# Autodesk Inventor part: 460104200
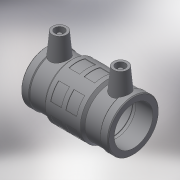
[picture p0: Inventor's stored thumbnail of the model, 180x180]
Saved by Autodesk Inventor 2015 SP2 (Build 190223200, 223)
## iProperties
Created: 2017-06
Part Number: 460104200
Material: Generic
Description: PLASSON LIGHTFIT COUPLER 200
Document SubType Name: Modeling
Designer: KIM
Mass: 89.5427 g
Surface Area: 304.58 cm^2
Volume: 89.5427 cm^3
Density: 1 g/cm^3
Appearance: Default
Author: KIM
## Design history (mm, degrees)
derived "460104.ipt"
feature "Solid1::460104.ipt"
tag "TaggingFeature1"
body "Solid1"
other parameters: "d13" = 232, "d14" = 17.6296, "d15" = 114, "d16" = 114, "d17" = 198, "d19" = 3.52592, "d20" = 168 deg, "d22" = 220.9, "d23" = 235, "d24" = 214.273, "d25" = 135 deg, "d26" = 92.8, "d27" = 135 deg, "d29" = 127, "d35" = 15, "d39" = 5 deg, "d44" = 4, "d46" = 14, "d47" = 0, "d52" = 230.3, "d53" = 11.6, "d54" = 11.6, "d55" = 11.6, "d56" = 35 deg, "d58" = 360 deg, "d60" = 22.8, "d61" = 135 deg, "d62" = 104.4, "d63" = 3, "d64" = 0, "L_" = 232, "L_1" = 114, "D_" = 235, "A_" = 127, "d_2" = 12
